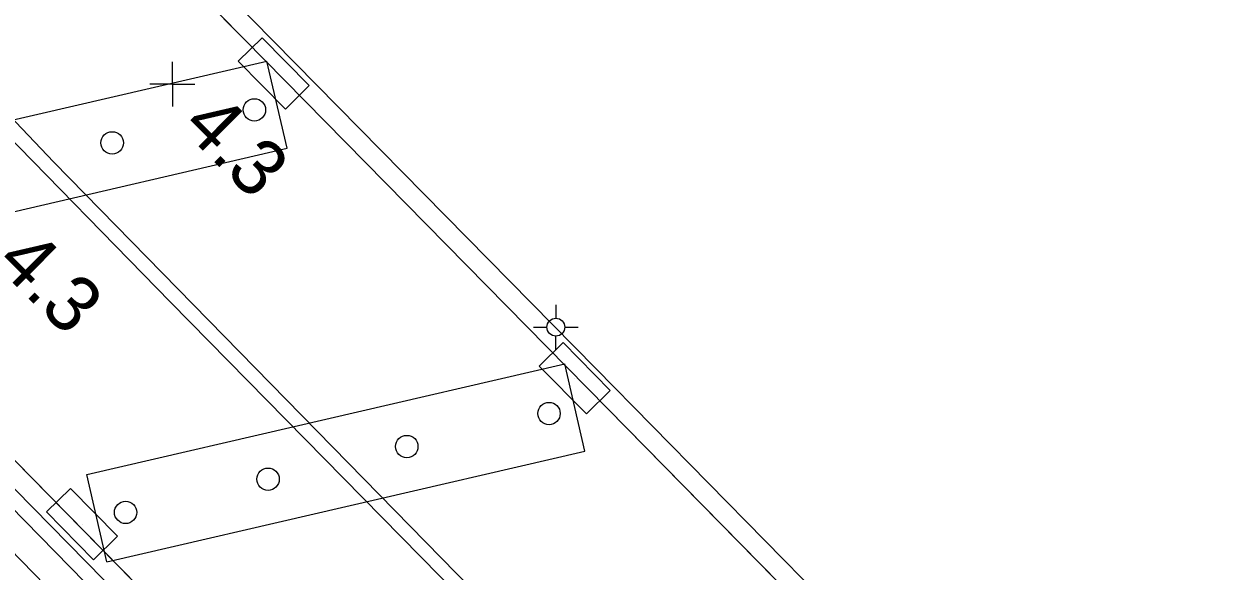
# Model space of a CAD drawing. Extents: x 1596643 to 1597288, y 13057194 to 13057957.
# Drawn here: x 1596994.5 to 1597047.6, y 13057381.1 to 13057405.5 of the extents above; entities that cross this region are included whole.
import ezdxf

# ---------------------------------------------------------------- set-up
doc = ezdxf.new("R2010")
doc.units = 0
for name, color, linetype in [('BAS belysningsstolpe P', 7, 'Continuous'), ('BAS bro kantbalk ej def L', 7, 'Continuous'), ('BAS dagvatten brunn P', 7, 'Continuous'), ('BAS jvg-bro kantbalk L', 7, 'Continuous'), ('BAS Level 16', 7, 'Continuous'), ('BAS markytetext T', 7, 'Continuous'), ('BAS väg-bro pelare stöd L', 7, 'Continuous'), ('BAS vägbanekant L', 7, 'Continuous')]:
    doc.layers.add(name, color=color, linetype=linetype)

msp = doc.modelspace()

# ---------------------------------------------------------------- linework, layer by layer
at = {"layer": 'BAS belysningsstolpe P'}
for p, q in [((1597018.296, 13057393), (1597018.296, 13057392.4)), ((1597018.296, 13057393), (1597018.296, 13057392.4)), ((1597017.296, 13057392), (1597017.896, 13057392)), ((1597017.296, 13057392), (1597017.896, 13057392)), ((1597018.695, 13057392), (1597019.296, 13057392)), ((1597018.695, 13057392), (1597019.296, 13057392)), ((1597018.296, 13057391), (1597018.296, 13057391.602)), ((1597018.296, 13057391), (1597018.296, 13057391.602))]:
    msp.add_line(p, q, dxfattribs=at)
msp.add_circle((1597018.296, 13057392), 0.4, dxfattribs=at)
msp.add_circle((1597018.296, 13057392), 0.4, dxfattribs=at)
at = {"layer": 'BAS bro kantbalk ej def L'}
for p, q in [((1596980.172, 13057396.033), (1597006.764, 13057368.984)), ((1596993.879, 13057384.028), (1597007.761, 13057369.925))]:
    msp.add_line(p, q, dxfattribs=at)
at = {"layer": 'BAS dagvatten brunn P'}
for p, q in [((1597005.683, 13057403.332), (1597005.683, 13057403.332)), ((1597005.683, 13057403.332), (1597005.683, 13057403.332)), ((1597019.143, 13057389.721), (1597019.143, 13057389.721)), ((1597019.143, 13057389.721), (1597019.143, 13057389.721)), ((1596997.108, 13057383.203), (1596997.108, 13057383.203)), ((1596997.108, 13057383.203), (1596997.108, 13057383.203))]:
    msp.add_line(p, q, dxfattribs=at)
for points in [[(1597004.096, 13057403.875), (1597006.201, 13057401.737), (1597007.27, 13057402.789), (1597005.165, 13057404.927)], [(1597004.096, 13057403.875), (1597006.201, 13057401.737), (1597007.27, 13057402.789), (1597005.165, 13057404.927)], [(1597017.556, 13057390.264), (1597019.661, 13057388.126), (1597020.73, 13057389.178), (1597018.625, 13057391.316)], [(1597017.556, 13057390.264), (1597019.661, 13057388.126), (1597020.73, 13057389.178), (1597018.625, 13057391.316)], [(1596995.521, 13057383.746), (1596997.626, 13057381.608), (1596998.695, 13057382.66), (1596996.59, 13057384.798)], [(1596995.521, 13057383.746), (1596997.626, 13057381.608), (1596998.695, 13057382.66), (1596996.59, 13057384.798)]]:
    msp.add_lwpolyline(points, close=True, dxfattribs=at)
at = {"layer": 'BAS jvg-bro kantbalk L'}
for p, q in [((1597003.245, 13057407.244), (1597020.09, 13057390.148)), ((1597020.09, 13057390.148), (1597033.863, 13057376.154)), ((1596991.946, 13057386.955), (1597003.562, 13057375.151))]:
    msp.add_line(p, q, dxfattribs=at)
at = {"layer": 'BAS Level 16'}
for q in [(1597001.146, 13057403.849), (1597001.146, 13057403.849), (1597000.146, 13057402.849), (1597000.146, 13057402.849), (1597002.146, 13057402.849), (1597001.146, 13057401.849), (1597002.146, 13057402.849), (1597001.146, 13057401.849)]:
    msp.add_line((1597001.146, 13057402.849), q, dxfattribs=at)
at = {"layer": 'BAS väg-bro pelare stöd L'}
for p, q in [((1596984, 13057398.936), (1597005.371, 13057403.887)), ((1597006.278, 13057399.991), (1597005.371, 13057403.887)), ((1596984.906, 13057395.04), (1597006.278, 13057399.991)), ((1596997.318, 13057385.412), (1597018.69, 13057390.363)), ((1597019.596, 13057386.467), (1597018.69, 13057390.363)), ((1596998.224, 13057381.516), (1597019.596, 13057386.467)), ((1596998.224, 13057381.516), (1596997.318, 13057385.412))]:
    msp.add_line(p, q, dxfattribs=at)
for centre in [(1597004.815, 13057401.704), (1596998.455, 13057400.23), (1597017.991, 13057388.142), (1597011.63, 13057386.668), (1597005.426, 13057385.209), (1596999.057, 13057383.728)]:
    msp.add_circle(centre, 0.5, dxfattribs=at)
at = {"layer": 'BAS vägbanekant L'}
for p, q in [((1597004.366, 13057404.842), (1596998.375, 13057410.918)), ((1597020.598, 13057388.374), (1597004.366, 13057404.842)), ((1597002.777, 13057377.214), (1596989.414, 13057390.809)), ((1597033.433, 13057375.328), (1597020.598, 13057388.374))]:
    msp.add_line(p, q, dxfattribs=at)
for points in [[(1597133.452, 13057259.15), (1597054.729, 13057339.299), (1596995.848, 13057399.372), (1596990.433, 13057405.034), (1596987.369, 13057408.321), (1596983.644, 13057412.319), (1596981.852, 13057414.308), (1596980.193, 13057416.206), (1596978.635, 13057418.012), (1596978.187, 13057418.58), (1596977.383, 13057419.585), (1596976.059, 13057421.351), (1596974.481, 13057423.493), (1596972.433, 13057426.487), (1596969.826, 13057430.508), (1596968.373, 13057432.851)], [(1596968.373, 13057431.554), (1596968.412, 13057431.491), (1596970.968, 13057427.583), (1596973.443, 13057423.938), (1596974.798, 13057422.081), (1596976.844, 13057419.442), (1596978.382, 13057417.442), (1596980.143, 13057415.392), (1596981.65, 13057413.616), (1596983.899, 13057411.12), (1596986.841, 13057408.015), (1596993.05, 13057401.308), (1597001.071, 13057393.121), (1597017.407, 13057376.512), (1597028.562, 13057365.159), (1597039.891, 13057353.552), (1597050.384, 13057342.909), (1597065.285, 13057327.589), (1597082.629, 13057309.925), (1597099.189, 13057293.124), (1597132.621, 13057259.15)], [(1597004.366, 13057404.842), (1596998.375, 13057410.918)], [(1597020.598, 13057388.374), (1597004.366, 13057404.842)], [(1597002.777, 13057377.214), (1596989.414, 13057390.809)], [(1597033.433, 13057375.328), (1597020.598, 13057388.374)]]:
    msp.add_lwpolyline(points, dxfattribs=at)

# ---------------------------------------------------------------- texts
at = {"layer": 'BAS markytetext T'}
for p in [(1597001.491, 13057400.899), (1596993.182, 13057394.808)]:
    msp.add_text('4.3', height=2.5, rotation=315, dxfattribs=at).set_placement(p)

doc.saveas('drawing.dxf')
